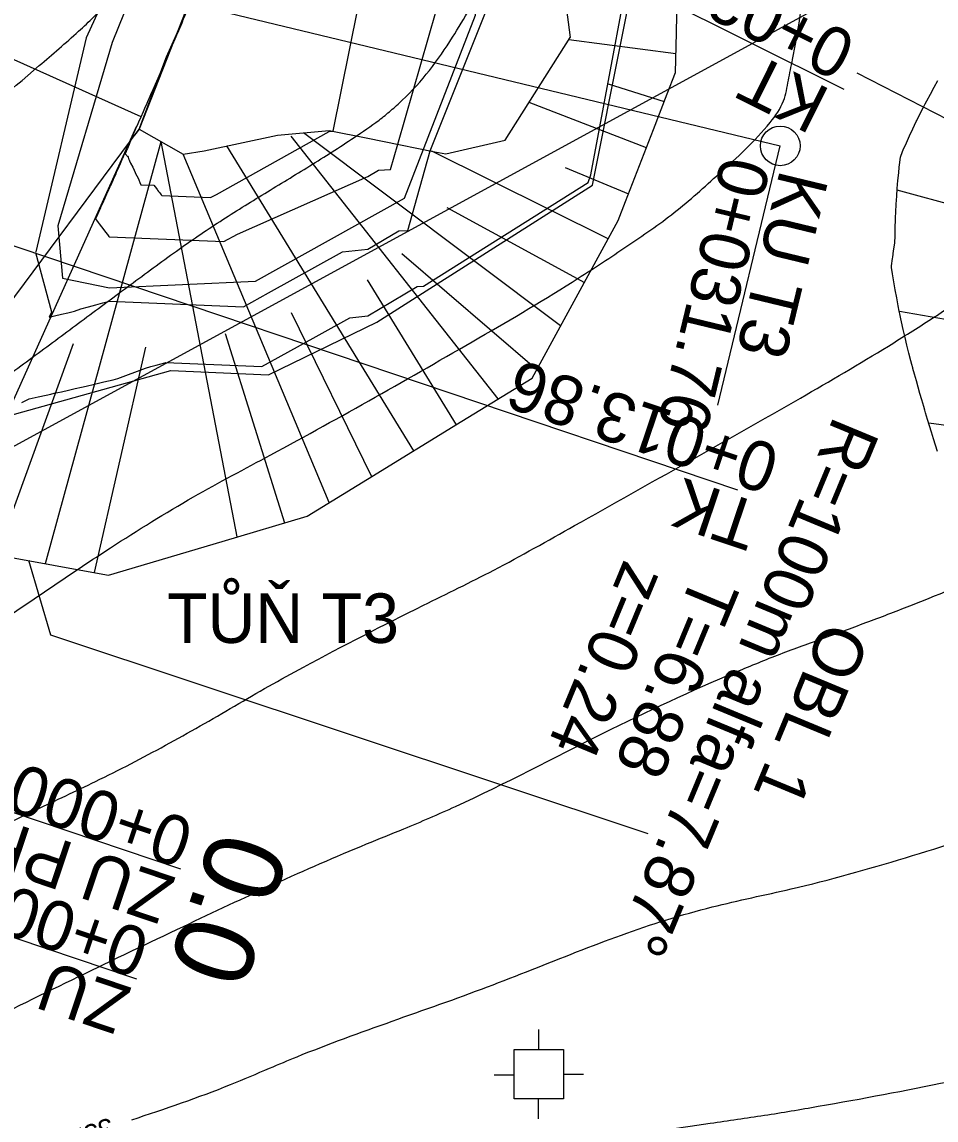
# Model space of a CAD drawing. Extents: x -564043 to -563833, y -1163561 to -1163412.
# Drawn here: x -563892.49 to -563869.43, y -1163520.81 to -1163493.12 of the extents above; entities that cross this region are included whole.
import ezdxf

# ---------------------------------------------------------------- set-up
doc = ezdxf.new("R2010")
doc.units = 0
for name, color, linetype in [('4', 7, 'Continuous'), ('5', 7, 'Continuous'), ('_popis staničení PH3', 7, 'Continuous'), ('_popis staničení T3', 7, 'Continuous'), ('Default', 7, 'Continuous'), ('Line', 7, 'Continuous'), ('Vrstva 24', 7, 'Continuous'), ('Vrstva 25', 7, 'Continuous'), ('Vrstva 26', 7, 'Continuous')]:
    doc.layers.add(name, color=color, linetype=linetype)

msp = doc.modelspace()

# ---------------------------------------------------------------- linework, layer by layer
for points in [[(-563900.324, -1163505.882), (-563892.678, -1163503.006), (-563888.735, -1163501.906), (-563886.271, -1163502.018), (-563883.536, -1163500.684), (-563878.095, -1163497.234), (-563876.621, -1163489.849), (-563880.163, -1163485.998), (-563881.977, -1163484.515), (-563883.765, -1163483.269), (-563890.133, -1163481.092), (-563891.974, -1163485.382), (-563895.143, -1163493.304), (-563898.704, -1163502.458), (-563900.439, -1163505.855)], [(-563887.058, -1163484.593), (-563887.855, -1163487.81), (-563890.21, -1163493.633), (-563891.581, -1163498.253), (-563891.461, -1163499.576), (-563890.275, -1163499.82), (-563886.599, -1163499.649), (-563882.84, -1163497.558), (-563881.049, -1163492.941), (-563880.784, -1163487.979), (-563884.81, -1163484.679), (-563886.418, -1163484.198)]]:
    msp.add_lwpolyline(points, close=True)
for points in [[(-563888.153, -1163487.579), (-563890.867, -1163493.518), (-563892.139, -1163498.917), (-563892.146, -1163498.931), (-563891.738, -1163500.429), (-563891.741, -1163500.435), (-563891.799, -1163500.561), (-563891.663, -1163500.529), (-563891.488, -1163500.487), (-563891.327, -1163500.449), (-563891.161, -1163500.409), (-563891.001, -1163500.348), (-563890.81, -1163500.297), (-563890.626, -1163500.247), (-563890.45, -1163500.199), (-563890.281, -1163500.153), (-563886.895, -1163500.296), (-563886.264, -1163499.949), (-563884.401, -1163498.91), (-563883.761, -1163498.848), (-563882.984, -1163498.383), (-563882.755, -1163498.371), (-563882.52, -1163497.536), (-563882.19, -1163496.364), (-563880.778, -1163492.835)], [(-563889.53, -1163495.82), (-563888.841, -1163493.998), (-563888.841, -1163493.998), (-563888.841, -1163493.998), (-563887.797, -1163491.659), (-563887.07, -1163489.251), (-563885.406, -1163487.811), (-563884.336, -1163488.791), (-563884.336, -1163488.791), (-563884.336, -1163488.791), (-563883.356, -1163488.989), (-563882.375, -1163489.186), (-563882.009, -1163489.26), (-563881.395, -1163489.384), (-563880.687, -1163489.526), (-563880.415, -1163489.581), (-563879.434, -1163489.779), (-563879.009, -1163490.8), (-563878.655, -1163493.506)], [(-563886.679, -1163488.563), (-563889.53, -1163495.82), (-563889.609, -1163495.921), (-563889.61, -1163495.921), (-563889.61, -1163495.922), (-563889.703, -1163496.041), (-563889.703, -1163496.041), (-563889.703, -1163496.041), (-563889.703, -1163496.041), (-563889.703, -1163496.041), (-563889.703, -1163496.041), (-563889.703, -1163496.041), (-563889.703, -1163496.041), (-563889.704, -1163496.041), (-563889.704, -1163496.041), (-563889.704, -1163496.041), (-563889.704, -1163496.041), (-563889.704, -1163496.042), (-563889.704, -1163496.042), (-563889.704, -1163496.042), (-563889.704, -1163496.042), (-563889.704, -1163496.042), (-563889.72, -1163496.062), (-563889.762, -1163496.158), (-563889.762, -1163496.159), (-563889.762, -1163496.159), (-563889.784, -1163496.208), (-563889.826, -1163496.303), (-563889.827, -1163496.305), (-563889.848, -1163496.352), (-563889.862, -1163496.385), (-563889.862, -1163496.385), (-563889.878, -1163496.423), (-563889.878, -1163496.423), (-563889.884, -1163496.438), (-563889.845, -1163496.481), (-563889.831, -1163496.497), (-563889.827, -1163496.502), (-563889.809, -1163496.522), (-563889.808, -1163496.523), (-563889.807, -1163496.524), (-563889.807, -1163496.525), (-563889.791, -1163496.589), (-563889.789, -1163496.591), (-563889.788, -1163496.593), (-563889.786, -1163496.595), (-563889.785, -1163496.597), (-563889.784, -1163496.598), (-563889.783, -1163496.6), (-563889.781, -1163496.602), (-563889.78, -1163496.604), (-563889.778, -1163496.606), (-563889.776, -1163496.609), (-563889.775, -1163496.61), (-563889.775, -1163496.611), (-563889.773, -1163496.613), (-563889.771, -1163496.615), (-563889.77, -1163496.618), (-563889.752, -1163496.678), (-563889.686, -1163496.777), (-563889.657, -1163496.853), (-563889.634, -1163496.915), (-563889.625, -1163496.937), (-563889.555, -1163497.058), (-563889.537, -1163497.1), (-563889.511, -1163497.165), (-563889.488, -1163497.222), (-563889.161, -1163497.23), (-563889.125, -1163497.277), (-563889.093, -1163497.319), (-563889.074, -1163497.343), (-563889.064, -1163497.356), (-563889.039, -1163497.39), (-563889.016, -1163497.42), (-563888.995, -1163497.447), (-563888.976, -1163497.472), (-563888.962, -1163497.491), (-563888.962, -1163497.491), (-563888.959, -1163497.494), (-563887.728, -1163497.546), (-563887.583, -1163497.467), (-563884.735, -1163495.88), (-563884.64, -1163495.87), (-563883.396, -1163489.693)], [(-563892.491, -1163502.712), (-563892.306, -1163502.622), (-563892.082, -1163502.572), (-563891.872, -1163502.525), (-563891.762, -1163502.501), (-563891.674, -1163502.481), (-563891.487, -1163502.439), (-563891.31, -1163502.398), (-563891.143, -1163502.36), (-563890.984, -1163502.324), (-563890.87, -1163502.298), (-563890.833, -1163502.289), (-563890.69, -1163502.256), (-563890.554, -1163502.224), (-563890.425, -1163502.194), (-563890.301, -1163502.165), (-563890.187, -1163502.138), (-563890.07, -1163502.109), (-563889.371, -1163501.843), (-563889.235, -1163501.806), (-563889.104, -1163501.771), (-563888.978, -1163501.736), (-563888.857, -1163501.703), (-563886.439, -1163501.806), (-563885.54, -1163501.311), (-563884.217, -1163500.574), (-563883.763, -1163500.529), (-563882.519, -1163499.786), (-563882.357, -1163499.777), (-563878.208, -1163497.166), (-563878.137, -1163496.97), (-563876.837, -1163490)], [(-563888.439, -1163493.108), (-563888.499, -1163493.245), (-563888.514, -1163493.28), (-563888.525, -1163493.307), (-563888.54, -1163493.34), (-563888.588, -1163493.451), (-563888.648, -1163493.589), (-563888.663, -1163493.623), (-563888.698, -1163493.705), (-563888.707, -1163493.725), (-563888.731, -1163493.781), (-563888.797, -1163493.933), (-563888.812, -1163493.966), (-563888.853, -1163494.062), (-563888.868, -1163494.095), (-563888.886, -1163494.138), (-563888.93, -1163494.239), (-563888.941, -1163494.264), (-563888.957, -1163494.301), (-563888.961, -1163494.31), (-563888.976, -1163494.345), (-563889.036, -1163494.482), (-563889.095, -1163494.617), (-563889.112, -1163494.654), (-563889.128, -1163494.691), (-563889.187, -1163494.826), (-563889.246, -1163494.958), (-563889.263, -1163494.997), (-563889.322, -1163495.129), (-563889.339, -1163495.169), (-563889.398, -1163495.3), (-563889.416, -1163495.341), (-563889.433, -1163495.381), (-563889.492, -1163495.514), (-563889.492, -1163495.514), (-563889.549, -1163495.643), (-563889.567, -1163495.685), (-563889.624, -1163495.814), (-563889.643, -1163495.857), (-563889.7, -1163495.985), (-563889.719, -1163496.029), (-563889.76, -1163496.121), (-563889.774, -1163496.154), (-563889.779, -1163496.166), (-563889.795, -1163496.203), (-563889.827, -1163496.274), (-563889.847, -1163496.32), (-563889.863, -1163496.355), (-563889.873, -1163496.38), (-563889.877, -1163496.389), (-563889.89, -1163496.418), (-563889.905, -1163496.453), (-563889.95, -1163496.557), (-563889.956, -1163496.571), (-563889.974, -1163496.61), (-563890.028, -1163496.734), (-563890.044, -1163496.77), (-563890.107, -1163496.911), (-563890.121, -1163496.943), (-563890.186, -1163497.088), (-563890.198, -1163497.116), (-563890.265, -1163497.265), (-563890.269, -1163497.275), (-563890.298, -1163497.339), (-563890.304, -1163497.352), (-563890.344, -1163497.442), (-563890.352, -1163497.46), (-563890.423, -1163497.618), (-563890.43, -1163497.632), (-563890.503, -1163497.795), (-563890.507, -1163497.804), (-563890.582, -1163497.972), (-563890.584, -1163497.975), (-563890.633, -1163498.083), (-563890.606, -1163498.118), (-563890.563, -1163498.174), (-563890.538, -1163498.206), (-563890.478, -1163498.284), (-563890.424, -1163498.355), (-563890.376, -1163498.419), (-563890.332, -1163498.478), (-563890.298, -1163498.523), (-563890.297, -1163498.523), (-563890.291, -1163498.531), (-563887.393, -1163498.653), (-563887.052, -1163498.466), (-563883.759, -1163497.017), (-563883.49, -1163496.856), (-563883.188, -1163496.84), (-563883.008, -1163496.199), (-563882.04, -1163492.836)], [(-563889.53, -1163495.82), (-563888.424, -1163496.447), (-563887.893, -1163496.363), (-563886.037, -1163495.972), (-563884.738, -1163495.851), (-563884.738, -1163495.851), (-563884.738, -1163495.851), (-563883.758, -1163496.048), (-563883.391, -1163496.122), (-563882.069, -1163496.388), (-563881.797, -1163496.443), (-563880.3, -1163496.1), (-563878.655, -1163493.506)], [(-563869.391, -1163503.951), (-563869.442, -1163503.788), (-563869.493, -1163503.625), (-563869.543, -1163503.462), (-563869.593, -1163503.299), (-563869.642, -1163503.137), (-563869.691, -1163502.974), (-563869.711, -1163502.905), (-563869.739, -1163502.812), (-563869.786, -1163502.649), (-563869.834, -1163502.487), (-563869.88, -1163502.324), (-563869.926, -1163502.162), (-563869.972, -1163502), (-563870.012, -1163501.857), (-563870.017, -1163501.838), (-563870.041, -1163501.751), (-563870.065, -1163501.66), (-563870.116, -1163501.464), (-563870.165, -1163501.268), (-563870.212, -1163501.071), (-563870.257, -1163500.873), (-563870.3, -1163500.674), (-563870.315, -1163500.606), (-563870.342, -1163500.475), (-563870.356, -1163500.406), (-563870.382, -1163500.275), (-563870.42, -1163500.075), (-563870.457, -1163499.874), (-563870.491, -1163499.672), (-563870.524, -1163499.47), (-563870.549, -1163499.308), (-563870.552, -1163499.268), (-563870.526, -1163499.077), (-563870.522, -1163499.047), (-563870.499, -1163498.886), (-563870.469, -1163498.695), (-563870.461, -1163498.499), (-563870.458, -1163498.302), (-563870.452, -1163498.104), (-563870.45, -1163498.053), (-563870.444, -1163497.906), (-563870.434, -1163497.716), (-563870.434, -1163497.709), (-563870.421, -1163497.511), (-563870.407, -1163497.314), (-563870.39, -1163497.117), (-563870.371, -1163496.92), (-563870.357, -1163496.779), (-563870.35, -1163496.723), (-563870.327, -1163496.526), (-563870.273, -1163496.384), (-563870.256, -1163496.344), (-563870.177, -1163496.164), (-563870.097, -1163495.985), (-563870.014, -1163495.807), (-563869.93, -1163495.63), (-563869.915, -1163495.6), (-563869.843, -1163495.454), (-563869.755, -1163495.279), (-563869.702, -1163495.177), (-563869.664, -1163495.105), (-563869.572, -1163494.933), (-563869.477, -1163494.761), (-563869.381, -1163494.59)], [(-563876.692, -1163513.593), (-563891.757, -1163508.582), (-563892.317, -1163506.699)]]:
    msp.add_lwpolyline(points)
at = {"layer": '4'}
for p, q in [((-563879.45, -1163519.025), (-563879.45, -1163518.525)), ((-563880.075, -1163519.675), (-563880.575, -1163519.675)), ((-563878.825, -1163519.65), (-563878.325, -1163519.65)), ((-563879.462, -1163520.275), (-563879.462, -1163520.775))]:
    msp.add_line(p, q, dxfattribs=at)
msp.add_lwpolyline([(-563880.075, -1163519.025), (-563878.825, -1163519.025), (-563878.825, -1163520.275), (-563880.075, -1163520.275)], close=True, dxfattribs=at)
at = {"layer": '5'}
for p, q in [((-563897.15, -1163506.247), (-563862.812, -1163487.513)), ((-563904.23, -1163488.796), (-563873.359, -1163496.24)), ((-563871.424, -1163494.398), (-563841.172, -1163509.993))]:
    msp.add_line(p, q, dxfattribs=at)
at = {"layer": '_popis staničení PH3'}
for points in [[(-563893.116, -1163484.167), (-563871.756, -1163494.81)], [(-563898.381, -1163496.847), (-563874.436, -1163504.911)], [(-563902.704, -1163509.683), (-563888.488, -1163514.47)], [(-563902.805, -1163509.983), (-563900.986, -1163513.414), (-563889.599, -1163517.249)]]:
    msp.add_lwpolyline(points, dxfattribs=at)
at = {"layer": '_popis staničení T3'}
msp.add_lwpolyline([(-563874.936, -1163502.781), (-563873.359, -1163496.24)], dxfattribs=at)
msp.add_circle((-563873.359, -1163496.24), 0.5, dxfattribs=at)
at = {"layer": 'Default'}
msp.add_lwpolyline([(-563894.011, -1163493.107), (-563894.298, -1163493.726), (-563896.807, -1163499.145), (-563896.925, -1163499.399), (-563897.869, -1163501.213), (-563898.286, -1163502.014), (-563899.415, -1163504.184), (-563898.029, -1163504.804), (-563894.792, -1163506.25), (-563894.189, -1163506.359), (-563890.445, -1163507.038), (-563890.304, -1163507.064), (-563887.435, -1163506.214), (-563885.296, -1163505.58), (-563883.769, -1163504.643), (-563881.393, -1163503.187), (-563879.621, -1163502.1), (-563877.447, -1163498.123), (-563877.26, -1163497.64), (-563876.56, -1163495.83), (-563876.213, -1163494.931), (-563876.002, -1163494.387), (-563875.979, -1163493.391), (-563875.957, -1163492.484)], dxfattribs=at)
at = {"layer": 'Line'}
for p, q in [((-563894.152, -1163493.411), (-563889.486, -1163495.501)), ((-563875.991, -1163493.924), (-563878.691, -1163493.563)), ((-563877.7, -1163494.675), (-563876.286, -1163495.121)), ((-563876.737, -1163496.287), (-563879.693, -1163495.144)), ((-563896.67, -1163505.411), (-563889.53, -1163495.82)), ((-563894.356, -1163506.329), (-563889.596, -1163495.749)), ((-563891.896, -1163506.775), (-563888.977, -1163496.134)), ((-563887.062, -1163506.103), (-563888.977, -1163496.134)), ((-563880.472, -1163502.622), (-563885.697, -1163495.995)), ((-563878.9, -1163500.783), (-563885.388, -1163495.911)), ((-563882.603, -1163503.929), (-563887.316, -1163496.241)), ((-563877.701, -1163498.589), (-563882.149, -1163496.372)), ((-563884.735, -1163505.236), (-563888.424, -1163496.447)), ((-563878.781, -1163496.785), (-563877.188, -1163497.453)), ((-563865.238, -1163498.779), (-563870.41, -1163497.354)), ((-563881.767, -1163497.791), (-563878.301, -1163499.686)), ((-563882.908, -1163498.955), (-563879.5, -1163501.88)), ((-563883.777, -1163499.623), (-563881.537, -1163503.276)), ((-563885.692, -1163500.44), (-563883.669, -1163504.582)), ((-563865.785, -1163501.217), (-563870.354, -1163500.416)), ((-563887.36, -1163500.969), (-563885.863, -1163505.748)), ((-563891.196, -1163501.236), (-563893.126, -1163506.552)), ((-563889.369, -1163501.316), (-563890.666, -1163506.998)), ((-563866.136, -1163503.692), (-563869.613, -1163503.234))]:
    msp.add_line(p, q, dxfattribs=at)
at = {"layer": 'Vrstva 24'}
for points in [[(-563866.364, -1163497.311), (-563866.075, -1163496.511), (-563865.895, -1163495.533), (-563865.845, -1163494.553), (-563865.947, -1163493.507), (-563866.272, -1163492.388), (-563866.563, -1163491.699), (-563866.868, -1163491.02), (-563867.192, -1163490.352), (-563867.536, -1163489.691), (-563869.125, -1163486.92), (-563869.85, -1163485.772), (-563870.624, -1163484.653), (-563871.666, -1163483.346), (-563872.824, -1163482.142), (-563874.562, -1163480.618), (-563875.472, -1163479.893), (-563878.363, -1163477.556), (-563882.755, -1163474.046), (-563884.234, -1163472.969), (-563885.61, -1163472.026), (-563886.998, -1163471.1), (-563889.83, -1163469.34), (-563892.347, -1163467.891)], [(-563852.947, -1163500.287), (-563852.983, -1163499.934), (-563853.278, -1163497.907), (-563853.324, -1163497.501), (-563853.384, -1163496.604), (-563853.408, -1163496.155), (-563853.449, -1163495.707), (-563853.76, -1163494.797), (-563854.364, -1163493.737), (-563856.816, -1163489.636), (-563859.313, -1163485.439), (-563859.915, -1163484.694), (-563860.397, -1163484.207), (-563862.509, -1163482.09), (-563867.011, -1163477.664), (-563868.116, -1163476.702), (-563871.116, -1163474.41), (-563872.986, -1163473.06), (-563873.689, -1163472.566), (-563878.103, -1163469.411), (-563878.316, -1163469.26)], [(-563905.221, -1163519.388), (-563901.417, -1163517.444), (-563900.291, -1163516.907), (-563895.909, -1163514.815), (-563892.135, -1163512.984), (-563890.63, -1163512.267), (-563888.864, -1163511.357), (-563887.99, -1163510.869), (-563887.125, -1163510.367), (-563886.26, -1163509.866), (-563885.383, -1163509.384), (-563882.362, -1163507.826), (-563880.585, -1163506.938), (-563878.549, -1163505.818), (-563872.848, -1163502.599), (-563870.632, -1163501.288), (-563869.542, -1163500.601), (-563868.575, -1163499.969)], [(-563889.716, -1163520.8), (-563887.224, -1163519.911), (-563886.24, -1163519.498), (-563885.546, -1163519.209), (-563880.746, -1163517.448), (-563876.224, -1163515.756), (-563875.074, -1163515.432), (-563873.084, -1163514.978), (-563867.347, -1163513.297), (-563865.289, -1163512.648), (-563863.244, -1163511.964), (-563861.209, -1163511.247), (-563859.18, -1163510.499), (-563858.534, -1163510.142), (-563854.776, -1163506.721), (-563853.738, -1163505.401), (-563853.175, -1163503.886), (-563853.155, -1163503.776)], [(-563878.638, -1163525.959), (-563876.035, -1163525.73), (-563873.358, -1163525.577), (-563872.019, -1163525.506), (-563870.681, -1163525.42), (-563867.228, -1163525.059), (-563863.791, -1163524.486), (-563862.262, -1163524.199), (-563857.791, -1163523.308), (-563852.826, -1163522.134), (-563851.58, -1163521.769), (-563850.041, -1163521.109), (-563844.975, -1163518.031), (-563844.52, -1163517.734), (-563844.289, -1163517.571), (-563843.081, -1163516.667), (-563842.493, -1163516.19), (-563841.914, -1163515.69), (-563841.532, -1163515.102), (-563841.398, -1163514.605), (-563841.069, -1163513.278)]]:
    msp.add_spline(points, degree=3, dxfattribs=at)
at = {"layer": 'Vrstva 25'}
msp.add_spline([(-563905.141, -1163510.37), (-563904.922, -1163510.229), (-563901.706, -1163508.177), (-563898.297, -1163505.868), (-563895.6, -1163504.013), (-563893.249, -1163502.324), (-563892.081, -1163501.469), (-563890.919, -1163500.608), (-563889.757, -1163499.746), (-563888.589, -1163498.892), (-563887.491, -1163498.145), (-563886.364, -1163497.441), (-563885.229, -1163496.747), (-563884.107, -1163496.03), (-563883.48, -1163495.59), (-563883.181, -1163495.349), (-563882.893, -1163495.092), (-563882.209, -1163494.336), (-563881.626, -1163493.502), (-563881.193, -1163492.783), (-563880.36, -1163491.213), (-563880.004, -1163490.417), (-563879.711, -1163489.616), (-563879.829, -1163489.186), (-563884.789, -1163483.345)], degree=3, dxfattribs=at)
at = {"layer": 'Vrstva 26'}
for points in [[(-563859.41, -1163497.306), (-563859.213, -1163496.32), (-563859.173, -1163495.343), (-563859.23, -1163495.062), (-563859.315, -1163494.786), (-563859.559, -1163494.264), (-563860.664, -1163492.33), (-563861.767, -1163490.395), (-563863.612, -1163487.077), (-563864.619, -1163485.435), (-563865.167, -1163484.642), (-563865.744, -1163483.864), (-563868.01, -1163481.46), (-563871.348, -1163478.665), (-563874.529, -1163476.131), (-563879.25, -1163472.365), (-563881.038, -1163471.025), (-563881.839, -1163470.479), (-563883.542, -1163469.415), (-563886.341, -1163467.718)], [(-563904.255, -1163504.408), (-563901.932, -1163502.584), (-563900.774, -1163501.667), (-563899.621, -1163500.744), (-563898.128, -1163499.495), (-563896.658, -1163498.219), (-563892.051, -1163494.217), (-563891.058, -1163493.351), (-563890.3, -1163492.602), (-563889.946, -1163492.201), (-563889.6, -1163491.789), (-563889.274, -1163491.333), (-563889.128, -1163491.092), (-563888.986, -1163490.845), (-563888.757, -1163490.393), (-563888.565, -1163489.929), (-563888.402, -1163489.454), (-563888.258, -1163488.97), (-563888.179, -1163488.634), (-563888.132, -1163488.29), (-563888.126, -1163487.946), (-563888.168, -1163487.609), (-563888.372, -1163487.087), (-563888.888, -1163486.275), (-563889.418, -1163485.493), (-563889.974, -1163484.737), (-563890.569, -1163484.004), (-563892.45, -1163481.915), (-563894.839, -1163479.601), (-563896.896, -1163477.665), (-563897.939, -1163476.713), (-563899, -1163475.779), (-563899.292, -1163475.563), (-563900.233, -1163474.949)], [(-563906.28, -1163515.803), (-563905.884, -1163515.571), (-563902.883, -1163513.741), (-563899.929, -1163512.038), (-563897.928, -1163511.018), (-563895.553, -1163509.778), (-563893.055, -1163508.246), (-563892.353, -1163507.782), (-563891.657, -1163507.311), (-563890.96, -1163506.841), (-563890.257, -1163506.379), (-563888.16, -1163505.094), (-563886.21, -1163504.031), (-563880.965, -1163501.085), (-563878.454, -1163499.578), (-563877.23, -1163498.772), (-563876.032, -1163497.922), (-563874.901, -1163496.941), (-563873.614, -1163495.651), (-563873.276, -1163495.107), (-563873.154, -1163494.587), (-563873.048, -1163494.066), (-563872.865, -1163493.019), (-563872.827, -1163492.778)], [(-563896.274, -1163519.554), (-563894.165, -1163518.707), (-563893.901, -1163518.593), (-563893.686, -1163518.487), (-563888.411, -1163515.922), (-563883.796, -1163513.845), (-563882.856, -1163513.463), (-563881.551, -1163512.898), (-563877.829, -1163511.052), (-563874.459, -1163509.5), (-563873.358, -1163509.055), (-563872.244, -1163508.643), (-563871.128, -1163508.237), (-563870.019, -1163507.811), (-563865.656, -1163505.903), (-563863.431, -1163504.67), (-563862.373, -1163503.951), (-563861.332, -1163503.174), (-563860.403, -1163502.078), (-563859.968, -1163500.761)], [(-563884.303, -1163523.029), (-563883.245, -1163522.781), (-563881.496, -1163522.368), (-563879.757, -1163521.916), (-563878.567, -1163521.564), (-563877.835, -1163521.362), (-563875.123, -1163520.885), (-563873.76, -1163520.686), (-563872.402, -1163520.46), (-563869.112, -1163519.839), (-563866.602, -1163519.331), (-563861.504, -1163518.34), (-563860.526, -1163518.047), (-563857.854, -1163516.895), (-563851.038, -1163513.844), (-563850.072, -1163513.304), (-563849.729, -1163513.002), (-563848.002, -1163510.368), (-563847.142, -1163508.464)]]:
    msp.add_spline(points, degree=3, dxfattribs=at)

# ---------------------------------------------------------------- texts
at = {"layer": '4'}
msp.add_text('TŮŇ T3', height=1.25, rotation=360, dxfattribs=at).set_placement((-563888.827, -1163508.776))
at = {"layer": '_popis staničení PH3'}
for s, height, rotation, p in [('0+027.60', 1.25, 153.5152, (-563871.381, -1163493.5)), ('KT ', 1.25, 153.5152, (-563872.05, -1163494.843)), ('0+013.86', 1.25, 161.3882, (-563873.306, -1163503.859)), ('R=100m alfa=7.87%%d', 1.25, 247.4517, (-563871.993, -1163503.016)), ('TK ', 1.25, 161.3882, (-563873.785, -1163505.28)), ('   z=0.24', 1.25, 247.4517, (-563876.754, -1163505.354)), ('  T=6.88', 1.25, 247.4517, (-563875.179, -1163506.125)), ('OBL 1', 1.25, 247.4517, (-563872.239, -1163508.172)), ('0+000.32', 1.25, 161.3882, (-563888.089, -1163513.285)), ('ZU PH3 ', 1.25, 161.3882, (-563888.568, -1163514.707)), ('0.0', 2, 251.3882, (-563887.624, -1163513.415)), ('0+000.00', 1.25, 161.3882, (-563889.201, -1163516.064)), ('ZU ', 1.25, 161.3882, (-563889.679, -1163517.486))]:
    msp.add_text(s, height=height, rotation=rotation, dxfattribs=at).set_placement(p)
at = {"layer": '_popis staničení T3'}
for s, p in [('0+031.76', (-563874.814, -1163496.452)), ('KU T3 ', (-563873.356, -1163496.804))]:
    msp.add_text(s, height=1.25, rotation=256.4433, dxfattribs=at).set_placement(p)
at = {"layer": 'Vrstva 25'}
msp.add_text('332.00', height=0.5, rotation=199.4037, dxfattribs=at).set_placement((-563890.267, -1163520.731))

doc.saveas('drawing.dxf')
